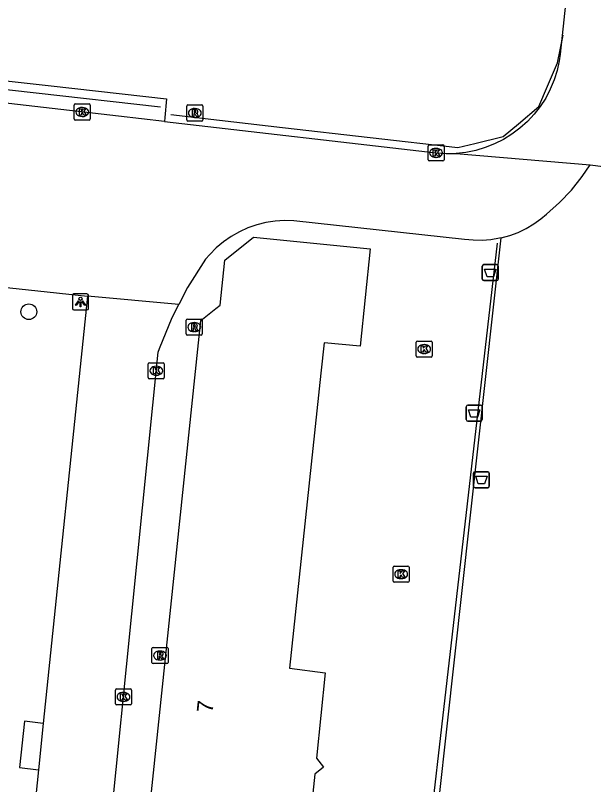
# Model space of a CAD drawing. Extents: x 162515 to 163909, y 388494 to 389773.
# Drawn here: x 162960.88 to 162996.88, y 388662.5 to 388710.39 of the extents above; entities that cross this region are included whole.
import ezdxf

# ---------------------------------------------------------------- set-up
doc = ezdxf.new("R2010")
doc.units = 0
for name, color, linetype in [('IMGEO_Afvalbak', 7, 'Continuous'), ('IMGEO_Boom', 7, 'Continuous'), ('IMGEO_Hek', 7, 'Continuous'), ('IMGEO_Kolk', 7, 'Continuous'), ('IMGEO_Lichtpunt', 7, 'Continuous'), ('IMGEO_Pand', 7, 'Continuous'), ('IMGEO_Pand_nummerreeks', 7, 'Continuous'), ('IMGEO_Rioolput', 7, 'Continuous'), ('IMGEO_Voetpad_open', 7, 'Continuous')]:
    doc.layers.add(name, color=color, linetype=linetype)

msp = doc.modelspace()

# ---------------------------------------------------------------- linework, layer by layer
at = {"layer": 'IMGEO_Afvalbak'}
for p, q in [((162990.051, 388694.873), (162990.841, 388694.873)), ((162990.841, 388694.873), (162990.051, 388694.873)), ((162989.951, 388693.973), (162989.951, 388694.773)), ((162989.951, 388694.773), (162989.951, 388693.973)), ((162990.941, 388694.773), (162990.941, 388693.973)), ((162990.941, 388693.973), (162990.941, 388694.773)), ((162990.841, 388693.873), (162990.051, 388693.873)), ((162990.051, 388693.873), (162990.841, 388693.873)), ((162988.951, 388685.221), (162988.951, 388686.021)), ((162988.951, 388686.021), (162988.951, 388685.221)), ((162989.051, 388686.121), (162989.841, 388686.121)), ((162989.841, 388686.121), (162989.051, 388686.121)), ((162989.941, 388686.021), (162989.941, 388685.221)), ((162989.941, 388685.221), (162989.941, 388686.021)), ((162989.841, 388685.121), (162989.051, 388685.121)), ((162989.051, 388685.121), (162989.841, 388685.121)), ((162989.395, 388681.08), (162989.395, 388681.88)), ((162989.395, 388681.88), (162989.395, 388681.08)), ((162989.495, 388681.98), (162990.285, 388681.98)), ((162990.285, 388681.98), (162989.495, 388681.98)), ((162990.385, 388681.88), (162990.385, 388681.08)), ((162990.385, 388681.08), (162990.385, 388681.88)), ((162990.285, 388680.98), (162989.495, 388680.98)), ((162989.495, 388680.98), (162990.285, 388680.98))]:
    msp.add_line(p, q, dxfattribs=at)
for points in [[(162990.094, 388694.587), (162990.798, 388694.587), (162990.649, 388694.117), (162990.243, 388694.117), (162990.094, 388694.587)], [(162989.094, 388685.835), (162989.798, 388685.835), (162989.649, 388685.365), (162989.243, 388685.365), (162989.094, 388685.835)], [(162989.538, 388681.694), (162990.242, 388681.694), (162990.093, 388681.224), (162989.687, 388681.224), (162989.538, 388681.694)]]:
    msp.add_lwpolyline(points, dxfattribs=at)
for centre, start, end in [((162990.051, 388694.773), 90, 180), ((162990.051, 388694.773), 90, 180), ((162990.841, 388694.773), 0, 90), ((162990.841, 388694.773), 360, 90), ((162990.051, 388693.973), 180, 270), ((162990.051, 388693.973), 180, 270), ((162990.841, 388693.973), 270, 0), ((162990.841, 388693.973), 270, 0), ((162989.051, 388686.021), 90, 180), ((162989.051, 388686.021), 90, 180), ((162989.841, 388686.021), 0, 90), ((162989.841, 388686.021), 360, 90), ((162989.051, 388685.221), 180, 270), ((162989.051, 388685.221), 180, 270), ((162989.841, 388685.221), 270, 0), ((162989.841, 388685.221), 270, 0), ((162989.495, 388681.88), 90, 180), ((162989.495, 388681.88), 90, 180), ((162990.285, 388681.88), 0, 90), ((162990.285, 388681.88), 360, 90), ((162989.495, 388681.08), 180, 270), ((162989.495, 388681.08), 180, 270), ((162990.285, 388681.08), 270, 0), ((162990.285, 388681.08), 270, 0)]:
    msp.add_arc(centre, 0.1, start, end, dxfattribs=at)
at = {"layer": 'IMGEO_Boom'}
msp.add_circle((162961.715, 388691.936), 0.489, dxfattribs=at)
at = {"layer": 'IMGEO_Hek'}
for points in [[(162994.631, 388707.425), (162994.988, 388709.154)], [(162943.832, 388707.61), (162954.409, 388706.43), (162969.911, 388704.701)], [(162970.548, 388704.21), (162977.506, 388703.415), (162988.427, 388702.167), (162989.476, 388702.418), (162991.248, 388702.843), (162992.205, 388703.644), (162993.477, 388704.708), (162994.015, 388705.974), (162994.631, 388707.425)], [(163028.546, 388625.664), (163000, 388628.878), (162983.359, 388630.752), (162990.894, 388696.199)]]:
    msp.add_lwpolyline(points, dxfattribs=at)
at = {"layer": 'IMGEO_Kolk'}
for p, q in [((162964.615, 388704.871), (162965.467, 388704.871)), ((162964.54, 388703.945), (162964.54, 388704.797)), ((162965.028, 388704.651), (162965.053, 388704.651)), ((162965.541, 388704.797), (162965.541, 388703.945)), ((162965.051, 388704.091), (162965.026, 388704.091)), ((162965.467, 388703.871), (162964.615, 388703.871)), ((162986.57, 388701.4), (162986.57, 388702.252)), ((162986.645, 388702.326), (162987.497, 388702.326)), ((162987.058, 388702.106), (162987.083, 388702.106)), ((162987.571, 388702.252), (162987.571, 388701.4)), ((162987.081, 388701.546), (162987.056, 388701.546)), ((162987.497, 388701.326), (162986.645, 388701.326)), ((162985.831, 388689.186), (162985.831, 388690.038)), ((162985.906, 388690.112), (162986.758, 388690.112)), ((162986.832, 388690.038), (162986.832, 388689.186)), ((162986.319, 388689.892), (162986.344, 388689.892)), ((162986.758, 388689.112), (162985.906, 388689.112)), ((162986.342, 388689.332), (162986.317, 388689.332)), ((162969.15, 388687.838), (162969.15, 388688.69)), ((162969.225, 388688.764), (162970.077, 388688.764)), ((162970.151, 388688.69), (162970.151, 388687.838)), ((162969.638, 388688.544), (162969.663, 388688.544)), ((162970.077, 388687.764), (162969.225, 388687.764)), ((162969.661, 388687.984), (162969.636, 388687.984)), ((162984.394, 388675.174), (162984.394, 388676.026)), ((162984.469, 388676.1), (162985.321, 388676.1)), ((162984.882, 388675.88), (162984.907, 388675.88)), ((162985.395, 388676.026), (162985.395, 388675.174)), ((162984.905, 388675.32), (162984.88, 388675.32)), ((162985.321, 388675.1), (162984.469, 388675.1)), ((162967.183, 388668.46), (162968.035, 388668.46)), ((162967.108, 388667.534), (162967.108, 388668.386)), ((162967.596, 388668.24), (162967.621, 388668.24)), ((162968.109, 388668.386), (162968.109, 388667.534)), ((162967.619, 388667.68), (162967.594, 388667.68)), ((162968.035, 388667.46), (162967.183, 388667.46))]:
    msp.add_line(p, q, dxfattribs=at)
for points in [[(162964.615, 388704.871), (162965.467, 388704.871)], [(162964.54, 388703.945), (162964.54, 388704.797)], [(162964.861, 388704.571), (162964.984, 388704.571), (162964.984, 388704.42), (162965.114, 388704.571), (162965.278, 388704.571), (162965.132, 388704.42), (162965.285, 388704.171), (162965.133, 388704.171), (162965.048, 388704.335), (162964.984, 388704.268), (162964.984, 388704.171), (162964.861, 388704.171), (162964.861, 388704.571)], [(162965.541, 388704.797), (162965.541, 388703.945)], [(162965.467, 388703.871), (162964.615, 388703.871)], [(162986.57, 388701.4), (162986.57, 388702.252)], [(162986.645, 388702.326), (162987.497, 388702.326)], [(162986.891, 388702.026), (162987.014, 388702.026), (162987.014, 388701.875), (162987.144, 388702.026), (162987.308, 388702.026), (162987.162, 388701.875), (162987.315, 388701.626), (162987.163, 388701.626), (162987.078, 388701.79), (162987.014, 388701.723), (162987.014, 388701.626), (162986.891, 388701.626), (162986.891, 388702.026)], [(162987.571, 388702.252), (162987.571, 388701.4)], [(162987.497, 388701.326), (162986.645, 388701.326)], [(162985.831, 388689.186), (162985.831, 388690.038)], [(162985.906, 388690.112), (162986.758, 388690.112)], [(162986.832, 388690.038), (162986.832, 388689.186)], [(162986.152, 388689.812), (162986.275, 388689.812), (162986.275, 388689.661), (162986.405, 388689.812), (162986.569, 388689.812), (162986.423, 388689.661), (162986.576, 388689.412), (162986.424, 388689.412), (162986.339, 388689.576), (162986.275, 388689.509), (162986.275, 388689.412), (162986.152, 388689.412), (162986.152, 388689.812)], [(162986.758, 388689.112), (162985.906, 388689.112)], [(162969.15, 388687.838), (162969.15, 388688.69)], [(162969.225, 388688.764), (162970.077, 388688.764)], [(162970.151, 388688.69), (162970.151, 388687.838)], [(162969.471, 388688.464), (162969.594, 388688.464), (162969.594, 388688.313), (162969.724, 388688.464), (162969.888, 388688.464), (162969.742, 388688.313), (162969.895, 388688.064), (162969.743, 388688.064), (162969.658, 388688.228), (162969.594, 388688.161), (162969.594, 388688.064), (162969.471, 388688.064), (162969.471, 388688.464)], [(162970.077, 388687.764), (162969.225, 388687.764)], [(162984.394, 388675.174), (162984.394, 388676.026)], [(162984.469, 388676.1), (162985.321, 388676.1)], [(162984.715, 388675.8), (162984.838, 388675.8), (162984.838, 388675.649), (162984.968, 388675.8), (162985.132, 388675.8), (162984.986, 388675.649), (162985.139, 388675.4), (162984.987, 388675.4), (162984.902, 388675.564), (162984.838, 388675.497), (162984.838, 388675.4), (162984.715, 388675.4), (162984.715, 388675.8)], [(162985.395, 388676.026), (162985.395, 388675.174)], [(162985.321, 388675.1), (162984.469, 388675.1)], [(162967.183, 388668.46), (162968.035, 388668.46)], [(162967.108, 388667.534), (162967.108, 388668.386)], [(162967.429, 388668.16), (162967.552, 388668.16), (162967.552, 388668.009), (162967.682, 388668.16), (162967.846, 388668.16), (162967.7, 388668.009), (162967.853, 388667.76), (162967.701, 388667.76), (162967.616, 388667.924), (162967.552, 388667.857), (162967.552, 388667.76), (162967.429, 388667.76), (162967.429, 388668.16)], [(162968.109, 388668.386), (162968.109, 388667.534)], [(162968.035, 388667.46), (162967.183, 388667.46)]]:
    msp.add_lwpolyline(points, dxfattribs=at)
for centre, start, end in [((162964.617, 388704.795), 91.552, 178.448), ((162964.617, 388704.795), 91.552, 178.448), ((162965.465, 388704.795), 1.552, 88.448), ((162965.465, 388704.795), 1.552, 88.448), ((162964.617, 388703.947), 181.552, 268.448), ((162964.617, 388703.947), 181.552, 268.448), ((162965.465, 388703.947), 271.552, 358.448), ((162965.465, 388703.947), 271.552, 358.448), ((162986.647, 388702.25), 91.552, 178.448), ((162986.647, 388702.25), 91.552, 178.448), ((162987.495, 388702.25), 1.552, 88.448), ((162987.495, 388702.25), 1.552, 88.448), ((162986.647, 388701.402), 181.552, 268.448), ((162986.647, 388701.402), 181.552, 268.448), ((162987.495, 388701.402), 271.552, 358.448), ((162987.495, 388701.402), 271.552, 358.448), ((162985.908, 388690.036), 91.552, 178.448), ((162985.908, 388690.036), 91.552, 178.448), ((162986.756, 388690.036), 1.552, 88.448), ((162986.756, 388690.036), 1.552, 88.448), ((162985.908, 388689.188), 181.552, 268.448), ((162985.908, 388689.188), 181.552, 268.448), ((162986.756, 388689.188), 271.552, 358.448), ((162986.756, 388689.188), 271.552, 358.448), ((162969.227, 388688.688), 91.552, 178.448), ((162969.227, 388688.688), 91.552, 178.448), ((162970.075, 388688.688), 1.552, 88.448), ((162970.075, 388688.688), 1.552, 88.448), ((162969.227, 388687.84), 181.552, 268.448), ((162969.227, 388687.84), 181.552, 268.448), ((162970.075, 388687.84), 271.552, 358.448), ((162970.075, 388687.84), 271.552, 358.448), ((162984.471, 388676.024), 91.552, 178.448), ((162984.471, 388676.024), 91.552, 178.448), ((162985.319, 388676.024), 1.552, 88.448), ((162985.319, 388676.024), 1.552, 88.448), ((162984.471, 388675.176), 181.552, 268.448), ((162984.471, 388675.176), 181.552, 268.448), ((162985.319, 388675.176), 271.552, 358.448), ((162985.319, 388675.176), 271.552, 358.448), ((162967.185, 388668.384), 91.552, 178.448), ((162967.185, 388668.384), 91.552, 178.448), ((162968.033, 388668.384), 1.552, 88.448), ((162968.033, 388668.384), 1.552, 88.448), ((162967.185, 388667.536), 181.552, 268.448), ((162967.185, 388667.536), 181.552, 268.448), ((162968.033, 388667.536), 271.552, 358.448), ((162968.033, 388667.536), 271.552, 358.448)]:
    msp.add_arc(centre, 0.0765, start, end, dxfattribs=at)
for centre, major_axis, ratio, start_param, end_param in [((162965.027, 388704.371), (-0.387, 0.002), 0.722429, 4.712389, 7.853982), ((162965.052, 388704.371), (-0.39, 0.002), 0.717154, 1.570796, 4.712389), ((162987.057, 388701.826), (-0.387, 0.002), 0.722429, 4.712389, 7.853982), ((162987.082, 388701.826), (-0.39, 0.002), 0.717154, 1.570796, 4.712389), ((162986.318, 388689.612), (-0.387, 0.002), 0.722429, 4.712389, 7.853982), ((162986.343, 388689.612), (-0.39, 0.002), 0.717154, 1.570796, 4.712389), ((162969.637, 388688.264), (-0.387, 0.002), 0.722429, 4.712389, 7.853982), ((162969.662, 388688.264), (-0.39, 0.002), 0.717154, 1.570796, 4.712389), ((162984.881, 388675.6), (-0.387, 0.002), 0.722429, 4.712389, 7.853982), ((162984.906, 388675.6), (-0.39, 0.002), 0.717154, 1.570796, 4.712389), ((162967.595, 388667.96), (-0.387, 0.002), 0.722429, 4.712389, 7.853982), ((162967.62, 388667.96), (-0.39, 0.002), 0.717154, 1.570796, 4.712389)]:
    msp.add_ellipse(centre, major_axis=major_axis, ratio=ratio, start_param=start_param, end_param=end_param, dxfattribs=at)
at = {"layer": 'IMGEO_Lichtpunt'}
for p, q in [((162964.433, 388692.947), (162964.433, 388692.14)), ((162964.433, 388692.947), (162964.433, 388692.14)), ((162965.335, 388693.042), (162964.527, 388693.042)), ((162965.335, 388693.042), (162964.527, 388693.042)), ((162965.429, 388692.14), (162965.429, 388692.947)), ((162965.429, 388692.14), (162965.429, 388692.947)), ((162964.527, 388692.046), (162965.335, 388692.046)), ((162964.527, 388692.046), (162965.335, 388692.046))]:
    msp.add_line(p, q, dxfattribs=at)
for points in [[(162964.807, 388692.611), (162964.846, 388692.583), (162964.658, 388692.321), (162964.62, 388692.348), (162964.807, 388692.611)], [(162964.909, 388692.563), (162964.956, 388692.563), (162964.956, 388692.241), (162964.909, 388692.241), (162964.909, 388692.563)], [(162965.019, 388692.583), (162965.057, 388692.61), (162965.244, 388692.348), (162965.205, 388692.32), (162965.019, 388692.583)]]:
    msp.add_lwpolyline(points, dxfattribs=at)
msp.add_circle((162964.932, 388692.745), 0.0994, dxfattribs=at)
for centre, start, end in [((162964.527, 388692.947), 90, 180), ((162964.527, 388692.947), 90, 180), ((162965.335, 388692.947), 0, 90), ((162965.335, 388692.947), 0, 90), ((162964.527, 388692.14), 180, 270), ((162964.527, 388692.14), 180, 270), ((162965.335, 388692.14), 270, 0), ((162965.335, 388692.14), 270, 360)]:
    msp.add_arc(centre, 0.0946, start, end, dxfattribs=at)
at = {"layer": 'IMGEO_Pand'}
msp.add_lwpolyline([(162973.983, 388641.944), (162973.11, 388643.02), (162967.425, 388643.61), (162972.414, 388691.394), (162973.366, 388692.148), (162973.619, 388692.348), (162973.91, 388695.143), (162975.704, 388696.571), (162982.959, 388695.844), (162982.355, 388689.801), (162980.1, 388689.993), (162979.9, 388688.105), (162977.948, 388669.744), (162980.165, 388669.466), (162979.616, 388664.152), (162980.058, 388663.595), (162979.532, 388663.147), (162979.315, 388661.183), (162979.757, 388660.621), (162979.202, 388660.172), (162978.034, 388648.858), (162979.834, 388646.664)], dxfattribs=at)
at = {"layer": 'IMGEO_Rioolput'}
for p, q in [((162971.55, 388703.883), (162971.55, 388704.735)), ((162971.625, 388704.809), (162972.477, 388704.809)), ((162972.038, 388704.589), (162972.063, 388704.589)), ((162972.551, 388704.735), (162972.551, 388703.883)), ((162972.061, 388704.029), (162972.036, 388704.029)), ((162972.477, 388703.809), (162971.625, 388703.809)), ((162971.588, 388691.478), (162972.44, 388691.478)), ((162971.513, 388690.552), (162971.513, 388691.404)), ((162972.001, 388691.258), (162972.026, 388691.258)), ((162972.514, 388691.404), (162972.514, 388690.552)), ((162972.024, 388690.698), (162971.999, 388690.698)), ((162972.44, 388690.478), (162971.588, 388690.478)), ((162969.381, 388670.11), (162969.381, 388670.962)), ((162969.456, 388671.036), (162970.308, 388671.036)), ((162970.382, 388670.962), (162970.382, 388670.11)), ((162969.869, 388670.816), (162969.894, 388670.816)), ((162970.308, 388670.036), (162969.456, 388670.036)), ((162969.892, 388670.256), (162969.867, 388670.256))]:
    msp.add_line(p, q, dxfattribs=at)
for points in [[(162971.55, 388703.883), (162971.55, 388704.735)], [(162971.625, 388704.809), (162972.477, 388704.809)], [(162972.139, 388704.507), (162971.887, 388704.509), (162971.887, 388704.109)], [(162972.065, 388704.428), (162972.011, 388704.428), (162972.011, 388704.347)], [(162972.551, 388704.735), (162972.551, 388703.883)], [(162971.887, 388704.109), (162972.011, 388704.109), (162972.011, 388704.271), (162972.022, 388704.271)], [(162972.011, 388704.347), (162972.063, 388704.347)], [(162972.069, 388704.242), (162972.14, 388704.109), (162972.28, 388704.109), (162972.215, 388704.235)], [(162972.477, 388703.809), (162971.625, 388703.809)], [(162971.588, 388691.478), (162972.44, 388691.478)], [(162971.513, 388690.552), (162971.513, 388691.404)], [(162972.102, 388691.176), (162971.85, 388691.178), (162971.85, 388690.778)], [(162972.028, 388691.097), (162971.974, 388691.097), (162971.974, 388691.016)], [(162971.974, 388691.016), (162972.026, 388691.016)], [(162972.514, 388691.404), (162972.514, 388690.552)], [(162971.85, 388690.778), (162971.974, 388690.778), (162971.974, 388690.94), (162971.985, 388690.94)], [(162972.032, 388690.911), (162972.103, 388690.778), (162972.243, 388690.778), (162972.178, 388690.904)], [(162972.44, 388690.478), (162971.588, 388690.478)], [(162969.381, 388670.11), (162969.381, 388670.962)], [(162969.456, 388671.036), (162970.308, 388671.036)], [(162970.382, 388670.962), (162970.382, 388670.11)], [(162969.97, 388670.734), (162969.718, 388670.736), (162969.718, 388670.336)], [(162969.718, 388670.336), (162969.842, 388670.336), (162969.842, 388670.498), (162969.853, 388670.498)], [(162969.896, 388670.655), (162969.842, 388670.655), (162969.842, 388670.574)], [(162969.842, 388670.574), (162969.894, 388670.574)], [(162969.9, 388670.469), (162969.971, 388670.336), (162970.111, 388670.336), (162970.046, 388670.462)], [(162970.308, 388670.036), (162969.456, 388670.036)]]:
    msp.add_lwpolyline(points, dxfattribs=at)
for centre, radius, start, end in [((162971.627, 388704.733), 0.0765, 91.552, 178.448), ((162971.627, 388704.733), 0.0765, 91.552, 178.448), ((162972.071, 388704.332), 0.0964, 77.0061, 93.1865), ((162972.085, 388704.389), 0.0378, 276.6634, 79.6772), ((162972.138, 388704.397), 0.109, 350.3612, 89.416), ((162972.136, 388704.397), 0.112, 277.5842, 350.9817), ((162972.475, 388704.733), 0.0765, 1.552, 88.448), ((162972.475, 388704.733), 0.0765, 1.552, 88.448), ((162972.021, 388704.218), 0.0533, 26.0293, 88.6989), ((162972.047, 388704.536), 0.19, 274.7715, 282.9687), ((162972.12, 388704.182), 0.108, 29.5134, 73.7905), ((162971.627, 388703.885), 0.0765, 181.552, 268.448), ((162971.627, 388703.885), 0.0765, 181.552, 268.448), ((162972.475, 388703.885), 0.0765, 271.552, 358.448), ((162972.475, 388703.885), 0.0765, 271.552, 358.448), ((162971.59, 388691.402), 0.0765, 91.552, 178.448), ((162971.59, 388691.402), 0.0765, 91.552, 178.448), ((162972.438, 388691.402), 0.0765, 1.552, 88.448), ((162972.438, 388691.402), 0.0765, 1.552, 88.448), ((162972.01, 388691.205), 0.19, 274.7715, 282.9687), ((162972.034, 388691.001), 0.0964, 77.0061, 93.1865), ((162972.048, 388691.058), 0.0378, 276.6634, 79.6772), ((162972.101, 388691.066), 0.109, 350.3612, 89.416), ((162972.099, 388691.066), 0.112, 277.5842, 350.9817), ((162971.59, 388690.554), 0.0765, 181.552, 268.448), ((162971.59, 388690.554), 0.0765, 181.552, 268.448), ((162971.984, 388690.887), 0.0533, 26.0293, 88.6989), ((162972.083, 388690.851), 0.108, 29.5134, 73.7905), ((162972.438, 388690.554), 0.0765, 271.552, 358.448), ((162972.438, 388690.554), 0.0765, 271.552, 358.448), ((162969.458, 388670.96), 0.0765, 91.552, 178.448), ((162969.458, 388670.96), 0.0765, 91.552, 178.448), ((162970.306, 388670.96), 0.0765, 1.552, 88.448), ((162970.306, 388670.96), 0.0765, 1.552, 88.448), ((162969.852, 388670.445), 0.0533, 26.0293, 88.6989), ((162969.878, 388670.763), 0.19, 274.7715, 282.9687), ((162969.902, 388670.559), 0.0964, 77.0061, 93.1865), ((162969.916, 388670.616), 0.0378, 276.6634, 79.6772), ((162969.969, 388670.624), 0.109, 350.3612, 89.416), ((162969.967, 388670.624), 0.112, 277.5842, 350.9817), ((162969.951, 388670.409), 0.108, 29.5134, 73.7905), ((162969.458, 388670.112), 0.0765, 181.552, 268.448), ((162969.458, 388670.112), 0.0765, 181.552, 268.448), ((162970.306, 388670.112), 0.0765, 271.552, 358.448), ((162970.306, 388670.112), 0.0765, 271.552, 358.448)]:
    msp.add_arc(centre, radius, start, end, dxfattribs=at)
for centre, major_axis, ratio, start_param, end_param in [((162972.037, 388704.309), (-0.387, 0.002), 0.722429, 4.712389, 7.853982), ((162972.062, 388704.309), (-0.39, 0.002), 0.717154, 1.570796, 4.712389), ((162972, 388690.978), (-0.387, 0.002), 0.722429, 4.712389, 7.853982), ((162972.025, 388690.978), (-0.39, 0.002), 0.717154, 1.570796, 4.712389), ((162969.868, 388670.536), (-0.387, 0.002), 0.722429, 4.712389, 7.853982), ((162969.893, 388670.536), (-0.39, 0.002), 0.717154, 1.570796, 4.712389)]:
    msp.add_ellipse(centre, major_axis=major_axis, ratio=ratio, start_param=start_param, end_param=end_param, dxfattribs=at)
at = {"layer": 'IMGEO_Voetpad_open'}
for points in [[(163005.689, 388806.988), (163005.427, 388804.551), (163000, 388755.61), (162999.38, 388750), (162995.492, 388714.399), (162994.789, 388707.964), (162994.733, 388707.565), (162994.603, 388706.959), (162994.418, 388706.366), (162994.182, 388705.792), (162993.895, 388705.241), (162993.56, 388704.718), (162993.179, 388704.228), (162992.757, 388703.773), (162992.295, 388703.358), (162991.798, 388702.985), (162991.27, 388702.659), (162990.715, 388702.381), (162990.137, 388702.154), (162989.541, 388701.979), (162988.932, 388701.858), (162988.315, 388701.792)], [(162943.308, 388706.87), (162943.526, 388708.174), (162963.112, 388705.997), (162970.291, 388705.199), (162970.189, 388704.028), (162970.167, 388703.781)], [(162970.167, 388703.781), (162967.307, 388704.111), (162946.434, 388706.523), (162943.308, 388706.87)], [(162970.167, 388703.781), (162987.075, 388701.827), (162987.694, 388701.782), (162988.315, 388701.792)], [(162988.315, 388701.792), (162996.661, 388701.08)], [(162991.121, 388696.533), (162991.655, 388696.681), (162992.174, 388696.877), (162992.673, 388697.118), (162993.149, 388697.403), (162993.597, 388697.729), (162993.937, 388698.021), (162994.749, 388698.729), (162995.495, 388699.507), (162996.168, 388700.349), (162996.661, 388701.08)], [(162996.661, 388701.08), (162998.917, 388700.798)], [(162991.121, 388696.533), (162991.026, 388696.512), (162990.483, 388696.421), (162989.934, 388696.378), (162989.384, 388696.385), (162988.836, 388696.441), (162978.211, 388697.605), (162977.628, 388697.618), (162977.046, 388697.578), (162976.471, 388697.487), (162975.905, 388697.345), (162975.355, 388697.152), (162974.824, 388696.912), (162974.316, 388696.624), (162973.837, 388696.293), (162973.389, 388695.92), (162972.976, 388695.509), (162972.711, 388695.202), (162971.59, 388693.436), (162971.049, 388692.387)], [(162983.875, 388631.042), (162991.121, 388696.533)], [(162958.574, 388693.639), (162965.366, 388692.914)], [(162965.366, 388692.914), (162962.617, 388666.303)], [(162971.049, 388692.387), (162965.366, 388692.914)], [(162963.647, 388628.636), (162963.767, 388629.826), (162963.893, 388631.072), (162965.179, 388643.845), (162969.769, 388689.43), (162969.843, 388689.64), (162970.632, 388691.577), (162971.049, 388692.387)], [(162962.617, 388666.303), (162961.448, 388666.446), (162961.127, 388663.557), (162962.318, 388663.417)], [(162962.617, 388666.303), (162962.318, 388663.417)], [(162962.318, 388663.417), (162958.059, 388622.192)]]:
    msp.add_lwpolyline(points, dxfattribs=at)

# ---------------------------------------------------------------- texts
at = {"layer": 'IMGEO_Pand_nummerreeks'}
msp.add_text('7', height=1, rotation=84.0424, dxfattribs=at).set_placement((162973.157, 388666.938))

doc.saveas('drawing.dxf')
